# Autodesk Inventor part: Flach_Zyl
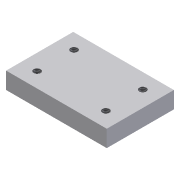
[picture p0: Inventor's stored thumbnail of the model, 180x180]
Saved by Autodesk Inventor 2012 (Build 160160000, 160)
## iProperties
Company: CAD-Verlag
Created: 2004-09
Part Number: Flach_Zyl
Document SubType Name: Modeling
Designer: Greiling
Manufacturer: Standard
Standards Organization: Custom
Density: 1 g/cm^3
Checked By: Jürgen Kronas
Stock Number: 10-10004
Material: Standard
Author: Juergen Kronas
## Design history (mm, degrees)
sketch "Skizze1"
  geometry: L1 (0, 28)-(0, -28) reference; L2 (-42, 0)-(42, 0) reference; L3 (-42, 0)-(42, 0) reference; L4 (0, -28)-(0, 28) reference; L5 (-30, 20)-(30, 20); L6 (30, 20)-(30, -20); L7 (30, -20)-(-30, -20); L8 (-30, -20)-(-30, 20); 1 further point
  constraints: 8 end point, 2 parallel, 1 horizontal, 1 perpendicular, 2 other
  dimensions: "d0" = 60 distance of L5.start L5.end; "d1" = 40 distance of L7.end L5.start
extrude "Extrusion1" new body sketch "Skizze1" distance "d2" = 10; taper "d3" = 0 deg
sketch "Skizze2"
  geometry: L1 (-30, -20)-(-30, 20) reference; L2 (30, -20)-(-30, -20) reference; L3 (0, 28)-(0, -28) reference; L4 (-42, 0)-(42, 0) reference; L5 (-42, 0)-(42, 0) reference; L6 (0, -28)-(0, 28) reference; 5 further points
  constraints: 1 horizontal, 1 vertical, 3 other
  dimensions: "d4" = 11 distance from line of L4 point (-20.5, 11); "d5" = 20.5 distance from line of L3 point (-20.5, 11); "d8" = 41 distance of point (-20.5, 11) point (20.5, 11); "d11" = 22 distance of point (-20.5, 11) point (-20.5, -11)
hole "Bohrung1" sketch "Skizze2" at (-20.5, 11), (20.5, 11), (-20.5, -11), (20.5, -11) diameter "d14" = 4.134; stored, may be unused: countersink angle "d18" = 90 deg, drill point angle "d20" = 118 deg; dims "d15" = 6, "d16" = 4, "d17" = 2, "d19" = 8
node "Volumenkörper1"
node "Volumenkörpern"
node "Oberflächenkörpern"
